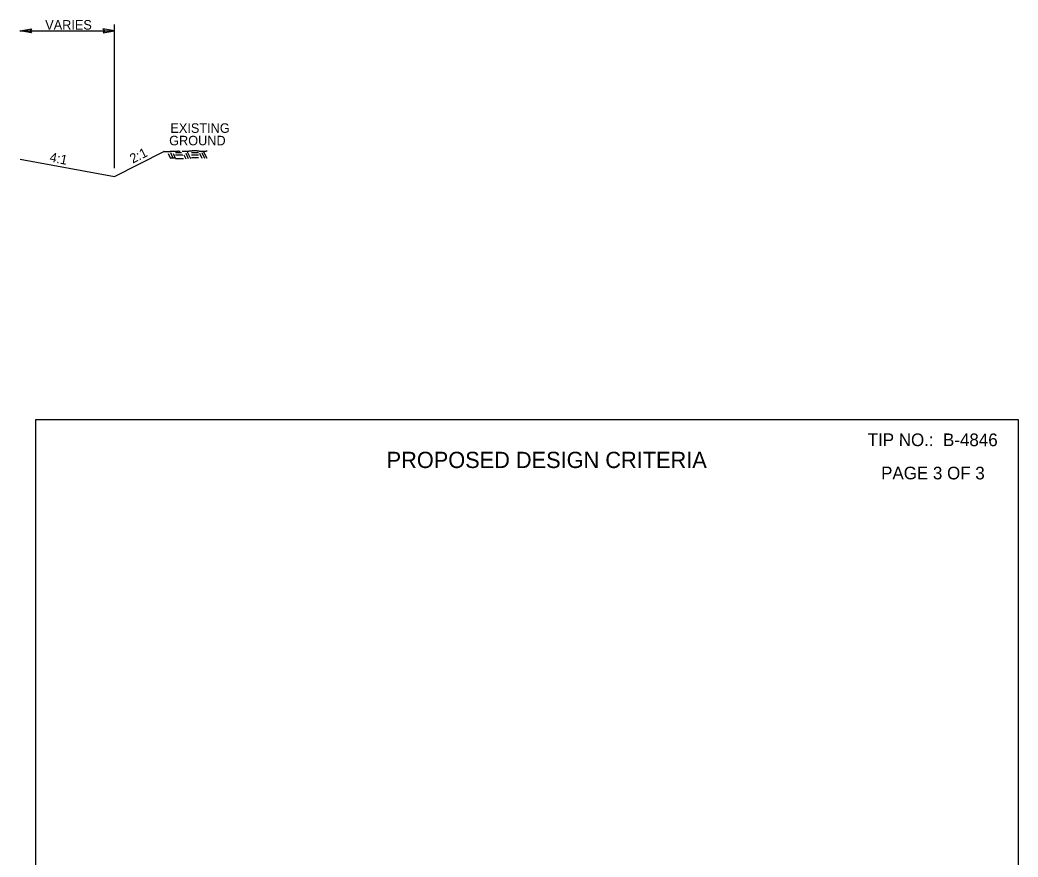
# Model space of a CAD drawing. Extents: x 1542177 to 1542464, y 45134 to 45344.
# Drawn here: x 1542400.7 to 1542463.7, y 45290.5 to 45343.3 of the extents above; entities that cross this region are included whole.
import ezdxf

# ---------------------------------------------------------------- set-up
doc = ezdxf.new("R2010")
doc.units = 0
doc.layers.add('Default', color=7, linetype='Continuous')

msp = doc.modelspace()

# ---------------------------------------------------------------- linework, layer by layer
at = {"layer": 'Default'}
for p, q in [((1542406.654, 45333.966), (1542406.654, 45343.031)), ((1542400.691, 45342.641), (1542406.654, 45342.641)), ((1542406.654, 45333.45), (1542409.779, 45335.013)), ((1542410.045, 45334.889), (1542410.187, 45334.586)), ((1542410.184, 45334.953), (1542410.349, 45334.599)), ((1542410.351, 45334.895), (1542410.486, 45334.606)), ((1542410.894, 45334.941), (1542410.517, 45334.941)), ((1542410.968, 45334.79), (1542410.517, 45334.79)), ((1542411.038, 45334.803), (1542411.153, 45334.553)), ((1542411.156, 45334.909), (1542411.312, 45334.571)), ((1542411.251, 45335.008), (1542411.448, 45334.587)), ((1542411.958, 45334.789), (1542411.51, 45334.789)), ((1542411.958, 45334.942), (1542411.511, 45334.942)), ((1542412.014, 45334.924), (1542412.162, 45334.605)), ((1542412.167, 45334.955), (1542412.332, 45334.607)), ((1542412.285, 45335.011), (1542412.476, 45334.597)), ((1542400.695, 45334.54), (1542406.654, 45333.45)), ((1542410.237, 45334.615), (1542410.518, 45334.614)), ((1542411.004, 45334.553), (1542410.509, 45334.553)), ((1542411.959, 45334.616), (1542411.511, 45334.615))]:
    msp.add_line(p, q, dxfattribs=at)
for points in [[(1542401.418, 45342.515), (1542400.698, 45342.639), (1542401.422, 45342.767), (1542401.33, 45342.639)], [(1542405.934, 45342.517), (1542406.654, 45342.641), (1542405.93, 45342.769), (1542406.022, 45342.641)]]:
    msp.add_lwpolyline(points, close=True, dxfattribs=at)
msp.add_lwpolyline([(1542401.69, 45318.108), (1542463.69, 45318.108), (1542463.69, 45236.508), (1542401.69, 45236.508), (1542401.69, 45318.108)], dxfattribs=at)
for points in [[(1542410.811, 45335.027), (1542410.808, 45335.028), (1542410.805, 45335.028), (1542410.803, 45335.028), (1542410.797, 45335.029), (1542410.791, 45335.028), (1542410.786, 45335.029), (1542410.783, 45335.029), (1542410.781, 45335.031), (1542410.779, 45335.031), (1542410.773, 45335.031), (1542410.767, 45335.031), (1542410.761, 45335.031), (1542410.753, 45335.03), (1542410.744, 45335.03), (1542410.736, 45335.03), (1542410.73, 45335.03), (1542410.723, 45335.032), (1542410.717, 45335.032), (1542410.711, 45335.033), (1542410.706, 45335.032), (1542410.7, 45335.032), (1542410.698, 45335.032), (1542410.695, 45335.032), (1542410.693, 45335.033), (1542410.687, 45335.033), (1542410.682, 45335.032), (1542410.676, 45335.032), (1542410.673, 45335.032), (1542410.671, 45335.033), (1542410.668, 45335.033), (1542410.662, 45335.033), (1542410.656, 45335.032), (1542410.65, 45335.032), (1542410.648, 45335.032), (1542410.645, 45335.032), (1542410.643, 45335.032), (1542410.64, 45335.032), (1542410.638, 45335.032), (1542410.635, 45335.032), (1542410.629, 45335.032), (1542410.624, 45335.032), (1542410.619, 45335.032), (1542410.613, 45335.032), (1542410.607, 45335.032), (1542410.6, 45335.032), (1542410.597, 45335.032), (1542410.593, 45335.032), (1542410.59, 45335.032), (1542410.585, 45335.032), (1542410.58, 45335.032), (1542410.575, 45335.032), (1542410.573, 45335.032), (1542410.57, 45335.032), (1542410.567, 45335.032), (1542410.565, 45335.032), (1542410.563, 45335.032), (1542410.561, 45335.032), (1542410.558, 45335.032), (1542410.556, 45335.032), (1542410.553, 45335.032), (1542410.551, 45335.032), (1542410.549, 45335.032), (1542410.547, 45335.032), (1542410.543, 45335.032), (1542410.539, 45335.032), (1542410.535, 45335.032), (1542410.533, 45335.032), (1542410.531, 45335.032), (1542410.528, 45335.032), (1542410.526, 45335.032), (1542410.523, 45335.032), (1542410.521, 45335.032), (1542410.519, 45335.032), (1542410.517, 45335.032), (1542410.515, 45335.032), (1542410.512, 45335.032), (1542410.51, 45335.032), (1542410.508, 45335.032), (1542410.506, 45335.032), (1542410.504, 45335.032), (1542410.503, 45335.032), (1542410.5, 45335.032), (1542410.497, 45335.032), (1542410.495, 45335.032), (1542410.492, 45335.032), (1542410.489, 45335.032), (1542410.487, 45335.032), (1542410.484, 45335.032), (1542410.481, 45335.032), (1542410.478, 45335.032), (1542410.475, 45335.032), (1542410.471, 45335.032), (1542410.468, 45335.032), (1542410.463, 45335.032), (1542410.458, 45335.032), (1542410.453, 45335.032), (1542410.451, 45335.031), (1542410.449, 45335.032), (1542410.446, 45335.032), (1542410.444, 45335.032), (1542410.442, 45335.03), (1542410.439, 45335.029), (1542410.437, 45335.029), (1542410.435, 45335.03), (1542410.433, 45335.03), (1542410.424, 45335.03), (1542410.416, 45335.028), (1542410.408, 45335.028), (1542410.402, 45335.029), (1542410.396, 45335.029), (1542410.39, 45335.029), (1542410.388, 45335.029), (1542410.385, 45335.029), (1542410.383, 45335.029), (1542410.38, 45335.029), (1542410.378, 45335.028), (1542410.375, 45335.027), (1542410.373, 45335.026), (1542410.37, 45335.025), (1542410.368, 45335.025), (1542410.366, 45335.024), (1542410.363, 45335.025), (1542410.361, 45335.025), (1542410.359, 45335.024), (1542410.357, 45335.023), (1542410.354, 45335.023), (1542410.348, 45335.022), (1542410.342, 45335.023), (1542410.336, 45335.023), (1542410.332, 45335.022), (1542410.329, 45335.021), (1542410.326, 45335.021), (1542410.323, 45335.021), (1542410.32, 45335.021), (1542410.317, 45335.021), (1542410.314, 45335.021), (1542410.31, 45335.022), (1542410.307, 45335.022), (1542410.305, 45335.022), (1542410.303, 45335.02), (1542410.3, 45335.02), (1542410.296, 45335.019), (1542410.291, 45335.019), (1542410.286, 45335.019), (1542410.283, 45335.019), (1542410.281, 45335.018), (1542410.279, 45335.018), (1542410.277, 45335.018), (1542410.274, 45335.018), (1542410.272, 45335.018), (1542410.27, 45335.018), (1542410.268, 45335.018), (1542410.265, 45335.018), (1542410.26, 45335.018), (1542410.254, 45335.018), (1542410.248, 45335.018), (1542410.245, 45335.018), (1542410.243, 45335.017), (1542410.24, 45335.016), (1542410.237, 45335.016), (1542410.235, 45335.016), (1542410.232, 45335.016), (1542410.23, 45335.016), (1542410.227, 45335.016), (1542410.225, 45335.016), (1542410.222, 45335.015), (1542410.22, 45335.014), (1542410.218, 45335.013), (1542410.216, 45335.013), (1542410.214, 45335.014), (1542410.212, 45335.014), (1542410.209, 45335.014), (1542410.206, 45335.015), (1542410.204, 45335.015), (1542410.201, 45335.015), (1542410.199, 45335.014), (1542410.196, 45335.014), (1542410.194, 45335.014), (1542410.192, 45335.012), (1542410.19, 45335.012), (1542410.188, 45335.012), (1542410.185, 45335.012), (1542410.183, 45335.012), (1542410.181, 45335.012), (1542410.178, 45335.013), (1542410.175, 45335.013), (1542410.173, 45335.013), (1542410.171, 45335.011), (1542410.169, 45335.011), (1542410.165, 45335.01), (1542410.161, 45335.011), (1542410.158, 45335.01), (1542410.155, 45335.01), (1542410.153, 45335.009), (1542410.151, 45335.009), (1542410.147, 45335.009), (1542410.144, 45335.01), (1542410.14, 45335.009), (1542410.138, 45335.009), (1542410.136, 45335.008), (1542410.134, 45335.007), (1542410.13, 45335.006), (1542410.127, 45335.005), (1542410.123, 45335.005), (1542410.119, 45335.005), (1542410.116, 45335.006), (1542410.112, 45335.006), (1542410.109, 45335.006), (1542410.107, 45335.006), (1542410.104, 45335.005), (1542410.096, 45335.005), (1542410.088, 45335.004), (1542410.079, 45335.003), (1542410.076, 45335.003), (1542410.072, 45335.003), (1542410.069, 45335.003), (1542410.066, 45335.003), (1542410.064, 45335.002), (1542410.061, 45335.001), (1542410.059, 45335.001), (1542410.057, 45335.001), (1542410.055, 45335.001), (1542410.052, 45335.001), (1542410.049, 45335.001), (1542410.047, 45335.001), (1542410.043, 45335.001), (1542410.039, 45335), (1542410.036, 45335), (1542410.034, 45335), (1542410.032, 45335), (1542410.03, 45335), (1542410.027, 45335), (1542410.024, 45335), (1542410.022, 45335), (1542410.018, 45335), (1542410.015, 45334.998), (1542410.012, 45334.998), (1542410.009, 45334.998), (1542410.007, 45334.998), (1542410.005, 45334.998), (1542410.002, 45334.998), (1542409.999, 45334.998), (1542409.996, 45334.998), (1542409.993, 45334.998), (1542409.99, 45334.996), (1542409.986, 45334.996), (1542409.984, 45334.996), (1542409.982, 45334.996), (1542409.979, 45334.996), (1542409.977, 45334.996), (1542409.974, 45334.996), (1542409.971, 45334.996), (1542409.962, 45334.996), (1542409.953, 45334.994), (1542409.944, 45334.994), (1542409.938, 45334.994), (1542409.932, 45334.995), (1542409.926, 45334.994), (1542409.924, 45334.994), (1542409.921, 45334.994), (1542409.919, 45334.994), (1542409.916, 45334.994), (1542409.914, 45334.994), (1542409.912, 45334.994), (1542409.906, 45334.995), (1542409.9, 45334.994), (1542409.894, 45334.994), (1542409.892, 45334.994), (1542409.89, 45334.996), (1542409.888, 45334.996), (1542409.881, 45334.996), (1542409.874, 45334.996), (1542409.868, 45334.996), (1542409.866, 45334.996), (1542409.863, 45334.996), (1542409.861, 45334.996), (1542409.859, 45334.996), (1542409.857, 45334.998), (1542409.855, 45334.998), (1542409.849, 45334.999), (1542409.843, 45334.997), (1542409.837, 45334.998), (1542409.835, 45334.999), (1542409.833, 45334.999), (1542409.831, 45335), (1542409.828, 45335), (1542409.825, 45335.001), (1542409.823, 45335.002), (1542409.82, 45335.002), (1542409.818, 45335.003), (1542409.816, 45335.003), (1542409.812, 45335.004), (1542409.808, 45335.006), (1542409.804, 45335.007), (1542409.801, 45335.008), (1542409.799, 45335.006), (1542409.796, 45335.007), (1542409.794, 45335.008), (1542409.792, 45335.009), (1542409.789, 45335.01), (1542409.787, 45335.01), (1542409.785, 45335.011), (1542409.783, 45335.012), (1542409.781, 45335.013), (1542409.78, 45335.013), (1542409.779, 45335.013)], [(1542412.515, 45335.04), (1542412.514, 45335.041), (1542412.514, 45335.042), (1542412.513, 45335.042), (1542412.51, 45335.044), (1542412.508, 45335.042), (1542412.506, 45335.042), (1542412.503, 45335.042), (1542412.501, 45335.043), (1542412.498, 45335.043), (1542412.496, 45335.042), (1542412.494, 45335.041), (1542412.492, 45335.04), (1542412.489, 45335.04), (1542412.487, 45335.039), (1542412.485, 45335.038), (1542412.482, 45335.038), (1542412.479, 45335.037), (1542412.477, 45335.037), (1542412.475, 45335.036), (1542412.473, 45335.035), (1542412.471, 45335.035), (1542412.468, 45335.034), (1542412.465, 45335.035), (1542412.462, 45335.035), (1542412.46, 45335.035), (1542412.458, 45335.033), (1542412.455, 45335.033), (1542412.453, 45335.033), (1542412.45, 45335.034), (1542412.448, 45335.033), (1542412.445, 45335.033), (1542412.443, 45335.032), (1542412.44, 45335.031), (1542412.438, 45335.031), (1542412.436, 45335.03), (1542412.434, 45335.029), (1542412.431, 45335.029), (1542412.429, 45335.029), (1542412.426, 45335.028), (1542412.424, 45335.028), (1542412.421, 45335.028), (1542412.419, 45335.028), (1542412.417, 45335.027), (1542412.414, 45335.027), (1542412.412, 45335.026), (1542412.41, 45335.026), (1542412.407, 45335.025), (1542412.404, 45335.024), (1542412.402, 45335.024), (1542412.4, 45335.025), (1542412.397, 45335.024), (1542412.395, 45335.024), (1542412.392, 45335.023), (1542412.39, 45335.022), (1542412.388, 45335.022), (1542412.386, 45335.021), (1542412.383, 45335.021), (1542412.38, 45335.02), (1542412.377, 45335.021), (1542412.374, 45335.021), (1542412.371, 45335.021), (1542412.369, 45335.019), (1542412.367, 45335.019), (1542412.363, 45335.018), (1542412.359, 45335.018), (1542412.355, 45335.019), (1542412.353, 45335.019), (1542412.351, 45335.019), (1542412.349, 45335.019), (1542412.345, 45335.019), (1542412.342, 45335.018), (1542412.338, 45335.018), (1542412.336, 45335.017), (1542412.333, 45335.017), (1542412.331, 45335.017), (1542412.328, 45335.017), (1542412.324, 45335.017), (1542412.321, 45335.017), (1542412.318, 45335.017), (1542412.316, 45335.017), (1542412.313, 45335.017), (1542412.309, 45335.017), (1542412.305, 45335.017), (1542412.302, 45335.017), (1542412.298, 45335.017), (1542412.295, 45335.017), (1542412.291, 45335.017), (1542412.289, 45335.017), (1542412.286, 45335.018), (1542412.284, 45335.018), (1542412.281, 45335.018), (1542412.279, 45335.017), (1542412.277, 45335.017), (1542412.273, 45335.017), (1542412.27, 45335.017), (1542412.267, 45335.017), (1542412.263, 45335.017), (1542412.259, 45335.017), (1542412.255, 45335.017), (1542412.253, 45335.017), (1542412.251, 45335.017), (1542412.248, 45335.017), (1542412.245, 45335.017), (1542412.242, 45335.017), (1542412.238, 45335.017), (1542412.235, 45335.017), (1542412.232, 45335.017), (1542412.229, 45335.017), (1542412.227, 45335.017), (1542412.225, 45335.016), (1542412.223, 45335.016), (1542412.221, 45335.016), (1542412.219, 45335.017), (1542412.216, 45335.017), (1542412.214, 45335.017), (1542412.212, 45335.017), (1542412.21, 45335.017), (1542412.207, 45335.017), (1542412.205, 45335.017), (1542412.203, 45335.017), (1542412.2, 45335.017), (1542412.198, 45335.017), (1542412.195, 45335.017), (1542412.192, 45335.017), (1542412.19, 45335.017), (1542412.187, 45335.016), (1542412.185, 45335.016), (1542412.183, 45335.016), (1542412.181, 45335.016), (1542412.179, 45335.016), (1542412.177, 45335.017), (1542412.174, 45335.017), (1542412.17, 45335.017), (1542412.166, 45335.016), (1542412.162, 45335.016), (1542412.16, 45335.016), (1542412.158, 45335.017), (1542412.155, 45335.017), (1542412.153, 45335.017), (1542412.152, 45335.017), (1542412.15, 45335.017), (1542412.146, 45335.017), (1542412.142, 45335.018), (1542412.138, 45335.019), (1542412.135, 45335.019), (1542412.133, 45335.019), (1542412.131, 45335.019), (1542412.128, 45335.019), (1542412.124, 45335.018), (1542412.121, 45335.018), (1542412.117, 45335.018), (1542412.113, 45335.021), (1542412.108, 45335.021), (1542412.105, 45335.021), (1542412.102, 45335.02), (1542412.098, 45335.021), (1542412.095, 45335.021), (1542412.091, 45335.022), (1542412.087, 45335.022), (1542412.084, 45335.023), (1542412.081, 45335.024), (1542412.078, 45335.024), (1542412.074, 45335.025), (1542412.07, 45335.024), (1542412.067, 45335.024), (1542412.064, 45335.025), (1542412.062, 45335.025), (1542412.06, 45335.026), (1542412.057, 45335.026), (1542412.055, 45335.027), (1542412.052, 45335.028), (1542412.048, 45335.028), (1542412.044, 45335.027), (1542412.04, 45335.028), (1542412.038, 45335.028), (1542412.036, 45335.028), (1542412.033, 45335.029), (1542412.031, 45335.03), (1542412.029, 45335.031), (1542412.026, 45335.031), (1542412.024, 45335.031), (1542412.022, 45335.031), (1542412.02, 45335.031), (1542412.014, 45335.032), (1542412.009, 45335.031), (1542412.003, 45335.033), (1542412, 45335.033), (1542411.998, 45335.034), (1542411.995, 45335.035), (1542411.993, 45335.036), (1542411.99, 45335.036), (1542411.988, 45335.037), (1542411.986, 45335.037), (1542411.983, 45335.036), (1542411.981, 45335.036), (1542411.977, 45335.037), (1542411.974, 45335.039), (1542411.97, 45335.04), (1542411.967, 45335.04), (1542411.965, 45335.04), (1542411.962, 45335.04), (1542411.959, 45335.041), (1542411.956, 45335.044), (1542411.953, 45335.044), (1542411.95, 45335.044), (1542411.948, 45335.043), (1542411.945, 45335.044), (1542411.943, 45335.044), (1542411.941, 45335.045), (1542411.938, 45335.046), (1542411.936, 45335.046), (1542411.934, 45335.047), (1542411.931, 45335.048), (1542411.929, 45335.049), (1542411.926, 45335.049), (1542411.923, 45335.049), (1542411.92, 45335.05), (1542411.916, 45335.05), (1542411.913, 45335.051), (1542411.91, 45335.051), (1542411.908, 45335.051), (1542411.905, 45335.051), (1542411.903, 45335.051), (1542411.902, 45335.053), (1542411.9, 45335.053), (1542411.897, 45335.053), (1542411.894, 45335.053), (1542411.891, 45335.053), (1542411.889, 45335.053), (1542411.886, 45335.053), (1542411.884, 45335.053), (1542411.881, 45335.053), (1542411.877, 45335.054), (1542411.873, 45335.054), (1542411.871, 45335.054), (1542411.868, 45335.054), (1542411.866, 45335.054), (1542411.864, 45335.054), (1542411.862, 45335.056), (1542411.86, 45335.056), (1542411.856, 45335.057), (1542411.852, 45335.056), (1542411.848, 45335.056), (1542411.846, 45335.056), (1542411.843, 45335.056), (1542411.841, 45335.056), (1542411.839, 45335.057), (1542411.837, 45335.058), (1542411.835, 45335.058), (1542411.832, 45335.058), (1542411.83, 45335.058), (1542411.827, 45335.058), (1542411.825, 45335.058), (1542411.823, 45335.058), (1542411.821, 45335.058), (1542411.818, 45335.058), (1542411.816, 45335.058), (1542411.813, 45335.058), (1542411.811, 45335.058), (1542411.809, 45335.058), (1542411.807, 45335.058), (1542411.804, 45335.058), (1542411.801, 45335.06), (1542411.799, 45335.06), (1542411.796, 45335.06), (1542411.794, 45335.059), (1542411.792, 45335.059), (1542411.789, 45335.059), (1542411.787, 45335.06), (1542411.784, 45335.06), (1542411.782, 45335.06), (1542411.78, 45335.059), (1542411.779, 45335.059), (1542411.774, 45335.059), (1542411.77, 45335.06), (1542411.765, 45335.06), (1542411.761, 45335.06), (1542411.757, 45335.06), (1542411.753, 45335.06), (1542411.75, 45335.06), (1542411.748, 45335.059), (1542411.745, 45335.059), (1542411.738, 45335.059), (1542411.731, 45335.06), (1542411.724, 45335.06), (1542411.722, 45335.06), (1542411.72, 45335.059), (1542411.717, 45335.059), (1542411.715, 45335.059), (1542411.713, 45335.059), (1542411.71, 45335.059), (1542411.708, 45335.059), (1542411.706, 45335.059), (1542411.703, 45335.059), (1542411.701, 45335.059), (1542411.698, 45335.06), (1542411.695, 45335.06), (1542411.692, 45335.059), (1542411.688, 45335.059), (1542411.684, 45335.059), (1542411.682, 45335.059), (1542411.679, 45335.059), (1542411.676, 45335.059), (1542411.674, 45335.059), (1542411.672, 45335.06), (1542411.67, 45335.06), (1542411.667, 45335.06), (1542411.665, 45335.059), (1542411.663, 45335.059), (1542411.66, 45335.059), (1542411.658, 45335.06), (1542411.656, 45335.06), (1542411.653, 45335.06), (1542411.651, 45335.059), (1542411.649, 45335.059), (1542411.646, 45335.059), (1542411.644, 45335.06), (1542411.642, 45335.06), (1542411.64, 45335.06), (1542411.638, 45335.06), (1542411.636, 45335.06), (1542411.632, 45335.059), (1542411.628, 45335.059), (1542411.625, 45335.058), (1542411.622, 45335.058), (1542411.619, 45335.058), (1542411.617, 45335.058), (1542411.614, 45335.058), (1542411.612, 45335.058), (1542411.61, 45335.058), (1542411.608, 45335.058), (1542411.605, 45335.058), (1542411.603, 45335.058), (1542411.601, 45335.058), (1542411.598, 45335.056), (1542411.596, 45335.056), (1542411.593, 45335.056), (1542411.591, 45335.056), (1542411.588, 45335.056), (1542411.586, 45335.056), (1542411.583, 45335.056), (1542411.581, 45335.056), (1542411.577, 45335.056), (1542411.574, 45335.056), (1542411.57, 45335.056), (1542411.568, 45335.056), (1542411.565, 45335.054), (1542411.563, 45335.054), (1542411.561, 45335.054), (1542411.558, 45335.054), (1542411.557, 45335.054), (1542411.554, 45335.054), (1542411.552, 45335.052), (1542411.549, 45335.052), (1542411.534, 45335.05), (1542411.518, 45335.048), (1542411.503, 45335.047), (1542411.501, 45335.047), (1542411.498, 45335.047), (1542411.496, 45335.047), (1542411.493, 45335.047), (1542411.491, 45335.045), (1542411.488, 45335.045), (1542411.486, 45335.045), (1542411.484, 45335.045), (1542411.482, 45335.045), (1542411.48, 45335.045), (1542411.477, 45335.046), (1542411.475, 45335.046), (1542411.472, 45335.046), (1542411.47, 45335.044), (1542411.467, 45335.044), (1542411.465, 45335.043), (1542411.463, 45335.043), (1542411.46, 45335.043), (1542411.454, 45335.043), (1542411.448, 45335.043), (1542411.442, 45335.043), (1542411.44, 45335.043), (1542411.437, 45335.042), (1542411.435, 45335.042), (1542411.433, 45335.041), (1542411.43, 45335.042), (1542411.428, 45335.042), (1542411.425, 45335.041), (1542411.423, 45335.04), (1542411.42, 45335.039), (1542411.412, 45335.039), (1542411.404, 45335.039), (1542411.396, 45335.038), (1542411.389, 45335.038), (1542411.382, 45335.037), (1542411.375, 45335.036), (1542411.372, 45335.036), (1542411.368, 45335.035), (1542411.364, 45335.035), (1542411.361, 45335.034), (1542411.357, 45335.033), (1542411.353, 45335.033), (1542411.351, 45335.032), (1542411.348, 45335.033), (1542411.345, 45335.033), (1542411.343, 45335.033), (1542411.341, 45335.031), (1542411.338, 45335.031), (1542411.336, 45335.03), (1542411.334, 45335.031), (1542411.332, 45335.031), (1542411.33, 45335.031), (1542411.327, 45335.03), (1542411.325, 45335.029), (1542411.321, 45335.029), (1542411.317, 45335.029), (1542411.314, 45335.029), (1542411.311, 45335.029), (1542411.309, 45335.028), (1542411.306, 45335.028), (1542411.303, 45335.028), (1542411.301, 45335.027), (1542411.298, 45335.027), (1542411.292, 45335.027), (1542411.287, 45335.028), (1542411.281, 45335.027), (1542411.277, 45335.027), (1542411.274, 45335.026), (1542411.27, 45335.026), (1542411.268, 45335.026), (1542411.265, 45335.026), (1542411.263, 45335.025), (1542411.258, 45335.025), (1542411.252, 45335.025), (1542411.246, 45335.025), (1542411.244, 45335.025), (1542411.242, 45335.025), (1542411.239, 45335.025), (1542411.237, 45335.025), (1542411.235, 45335.024), (1542411.232, 45335.024), (1542411.23, 45335.023), (1542411.227, 45335.023), (1542411.225, 45335.023), (1542411.219, 45335.024), (1542411.213, 45335.024), (1542411.207, 45335.024), (1542411.204, 45335.024), (1542411.202, 45335.024), (1542411.2, 45335.024), (1542411.197, 45335.024), (1542411.195, 45335.022), (1542411.192, 45335.022), (1542411.19, 45335.022), (1542411.187, 45335.022), (1542411.185, 45335.022), (1542411.179, 45335.022), (1542411.173, 45335.022), (1542411.167, 45335.022), (1542411.165, 45335.022), (1542411.163, 45335.022), (1542411.16, 45335.022), (1542411.157, 45335.022), (1542411.155, 45335.022), (1542411.152, 45335.022), (1542411.146, 45335.022), (1542411.141, 45335.02), (1542411.136, 45335.02), (1542411.134, 45335.02), (1542411.131, 45335.02), (1542411.129, 45335.02), (1542411.124, 45335.02), (1542411.12, 45335.02), (1542411.115, 45335.02), (1542411.112, 45335.02), (1542411.109, 45335.02), (1542411.106, 45335.02), (1542411.1, 45335.02), (1542411.094, 45335.02), (1542411.088, 45335.02), (1542411.08, 45335.02), (1542411.071, 45335.02), (1542411.063, 45335.02), (1542411.057, 45335.02), (1542411.051, 45335.018), (1542411.045, 45335.018), (1542411.043, 45335.018), (1542411.041, 45335.018), (1542411.04, 45335.018), (1542411.037, 45335.018), (1542411.035, 45335.018), (1542411.032, 45335.018), (1542411.026, 45335.018), (1542411.02, 45335.018), (1542411.013, 45335.018), (1542411.011, 45335.018), (1542411.009, 45335.019), (1542411.007, 45335.019), (1542411.004, 45335.018), (1542411.003, 45335.016), (1542411, 45335.016), (1542410.998, 45335.016), (1542410.995, 45335.016), (1542410.992, 45335.016), (1542410.99, 45335.016), (1542410.988, 45335.016), (1542410.986, 45335.016), (1542410.983, 45335.016), (1542410.981, 45335.016), (1542410.978, 45335.016), (1542410.976, 45335.016), (1542410.974, 45335.015), (1542410.971, 45335.014), (1542410.968, 45335.014), (1542410.966, 45335.014), (1542410.963, 45335.014), (1542410.96, 45335.014), (1542410.958, 45335.015), (1542410.956, 45335.015), (1542410.954, 45335.015), (1542410.952, 45335.015), (1542410.949, 45335.015), (1542410.947, 45335.015), (1542410.944, 45335.015), (1542410.942, 45335.015), (1542410.939, 45335.015), (1542410.937, 45335.012), (1542410.935, 45335.012), (1542410.935, 45335.012), (1542410.935, 45335.012), (1542410.935, 45335.012)]]:
    msp.add_open_spline(points, degree=3, dxfattribs=at)

# ---------------------------------------------------------------- texts
for s, height, p in [('VARIES', 0.6, (1542402.285, 45342.718)), ('EXISTING', 0.6, (1542410.186, 45336.2)), ('GROUND', 0.6, (1542410.108, 45335.413)), ('PROPOSED DESIGN CRITERIA', 1.02627, (1542423.836, 45315.037))]:
    msp.add_text(s, height=height, dxfattribs=at).set_placement(p)
for s, height, rotation, p in [('4:1', 0.6, 348.73266, (1542402.526, 45334.393)), ('2:1', 0.6, 26.56505, (1542407.805, 45334.252)), ('TIP NO.:  B-4846', 0.8, 359.9469, (1542454.2, 45316.424)), ('PAGE 3 OF 3', 0.8, 359.9469, (1542455.047, 45314.325))]:
    msp.add_text(s, height=height, rotation=rotation, dxfattribs=at).set_placement(p)

doc.saveas('drawing.dxf')
